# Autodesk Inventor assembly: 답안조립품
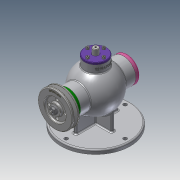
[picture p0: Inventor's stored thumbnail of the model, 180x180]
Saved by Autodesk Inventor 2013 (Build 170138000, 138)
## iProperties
Created: 2020-08
Part Number: 답안조립품
Document SubType Name: Assembly
Designer: user
Author: user
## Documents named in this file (18)
- C:\Users\user\Desktop\700806V1010\답안조립품.iam
- C:\Users\user\Desktop\700806V1010\본체.ipt
- C:\Users\user\Desktop\700806V1010\Ű 3x3x12.ipt
- C:\Users\user\Desktop\700806V1010\V-벨트풀리.ipt
- C:\Users\user\Desktop\700806V1010\너트 M8.ipt
- C:\Users\user\Desktop\700806V1010\뒤커버.ipt
- C:\Users\user\Desktop\700806V1010\멈춤링 15x1.ipt
- C:\Users\user\Desktop\700806V1010\멈춤링 35x1.6.ipt
- 멈춤링 35x1.6.ipt
- C:\Users\user\Desktop\700806V1010\베어링 6202.ipt
- 베어링 6202.ipt
- C:\Users\user\Desktop\700806V1010\볼트 M4.ipt
- C:\Users\user\Desktop\700806V1010\상부커버.ipt
- C:\Users\user\Desktop\700806V1010\슬라이드.ipt
- C:\Users\user\Desktop\700806V1010\앞커버.ipt
- C:\Users\user\Desktop\700806V1010\오일 실 15 30 7.ipt
- C:\Users\user\Desktop\700806V1010\칼라.ipt
- C:\Users\user\Desktop\700806V1010\편심축.ipt
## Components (2 placed, 2 different names)
1. Ű 3x3x12:1
2. V-벨트풀리:1
